Omron CX-Programmer project 新規ﾌﾟﾛｼﾞｪｸﾄ (CX-Programmer 9.76)

# PLC 新規PLC1: CJ2M CPU11
I/O table (CPU CJ2M-CPU11): rack 0 slot 0 CJ1W-ETN21(ETN21Mode)

## Program 新規ﾌﾟﾛｸﾞﾗﾑ1 (cyclic task 0)
Local symbols
ETN_TCPｺﾈｸｼｮﾝ状態 D30016 UINT  ; ETNﾕﾆｯﾄ用TCPｺﾈｸｼｮﾝ状態
ETN_TCP受信ﾃﾞｰﾀﾊﾞｲﾄ数 D30008 UINT  ; ETNﾕﾆｯﾄ用TCP受信ﾃﾞｰﾀﾊﾞｲﾄ数
ETN_ｵｰﾌﾟﾝ要求 1522.10 BOOL  ; ETNﾕﾆｯﾄ用TCPｵｰﾌﾟﾝ要求(ACTIVE)特定ﾋﾞｯﾄ
ETN_ｸﾛｰｽﾞ要求 1522.13 BOOL  ; ETNﾕﾆｯﾄ用ｸﾛｰｽﾞ要求特定ﾋﾞｯﾄ
ETN_ｿｹｯﾄNo8 D30088 UINT  ; ETNﾕﾆｯﾄ用ｿｹｯﾄｵﾌﾟｼｮﾝ / ｿｹｯﾄNo.8
ETN_ﾀｲﾑｱｳﾄ値 D30096 UINT  ; ETNﾕﾆｯﾄ用ﾀｲﾑｱｳﾄ値
ETN_自ﾎﾟｰﾄNo D30089 UINT  ; ETNﾕﾆｯﾄ用自ﾎﾟｰﾄNo.
ETN_受信ﾃﾞｰﾀあり 1516.13 BOOL  ; ETNﾕﾆｯﾄ用受信ﾃﾞｰﾀあり/なし判定ﾋﾞｯﾄ
ETN_受信要求 1522.12 BOOL  ; ETNﾕﾆｯﾄ用受信要求特定ﾋﾞｯﾄ
ETN_終了ｺｰﾄﾞ D30097 UINT  ; ETNﾕﾆｯﾄ用終了ｺｰﾄﾞ
ETN_相手IPｱﾄﾞﾚｽ_1 D30090 UINT  ; ETNﾕﾆｯﾄ用相手IPｱﾄﾞﾚｽ
ETN_相手IPｱﾄﾞﾚｽ_2 D30091 UINT  ; ETNﾕﾆｯﾄ用相手IPｱﾄﾞﾚｽ
ETN_相手ﾎﾟｰﾄNo D30092 UINT  ; ETNﾕﾆｯﾄ用相手ﾎﾟｰﾄNo.
ETN_送受信ﾃﾞｰﾀｱﾄﾞﾚｽ_1 D30094 UINT  ; ETNﾕﾆｯﾄ用送信/受信ﾃﾞｰﾀｱﾄﾞﾚｽ
ETN_送受信ﾃﾞｰﾀｱﾄﾞﾚｽ_2 D30095 UINT  ; ETNﾕﾆｯﾄ用送信/受信ﾃﾞｰﾀｱﾄﾞﾚｽ
ETN_送受信ﾃﾞｰﾀﾊﾞｲﾄ数 D30093 INT  ; ETNﾕﾆｯﾄ用送信/受信ﾃﾞｰﾀﾊﾞｲﾄ数
ETN_送信要求 1522.11 BOOL  ; ETNﾕﾆｯﾄ用送信要求特定ﾋﾞｯﾄ
出力_ｵｰﾌﾟﾝ異常ｺｰﾄﾞ H400 WORD  ; ｵｰﾌﾟﾝ処理の終了ｺｰﾄﾞ/ﾀｲﾑｱｳﾄｺｰﾄﾞ
出力_ｸﾛｰｽﾞ異常ｺｰﾄﾞ H404 WORD  ; ｸﾛｰｽﾞ処理の終了ｺｰﾄﾞ/ﾀｲﾑｱｳﾄｺｰﾄﾞ
出力_受信ﾃﾞｰﾀ D10001 WORD[2000]  ; 受信ﾃﾞｰﾀ格納ｴﾘｱ
出力_受信ﾃﾞｰﾀﾊﾞｲﾄ数 D10000 INT  ; 受信ﾃﾞｰﾀﾊﾞｲﾄ数格納ｴﾘｱ
出力_受信異常ｺｰﾄﾞ H402 WORD  ; 受信処理の終了ｺｰﾄﾞ/ﾀｲﾑｱｳﾄｺｰﾄﾞ
出力_相手機器異常ｺｰﾄﾞ H403 WORD  ; 相手機器の終了ｺｰﾄﾞ/応答ｺｰﾄﾞ
出力_送信異常ｺｰﾄﾞ H401 WORD  ; 送信処理の終了ｺｰﾄﾞ/ﾀｲﾑｱｳﾄｺｰﾄﾞ
内部_TCPｺﾈｸｼｮﾝ状態 5005 UINT  ; TCPｺﾈｸｼｮﾝ状態判定ｴﾘｱ
内部_ｵｰﾌﾟﾝﾀｲﾑｱｳﾄ 5001.04 BOOL  ; ﾀｲﾑｱｳﾄ
内部_ｵｰﾌﾟﾝ異常終了 5001.02 BOOL  ; 異常終了→【ｸﾛｰｽﾞ処理へ】
内部_ｵｰﾌﾟﾝ監視ﾀｲﾏON T1000 BOOL  ; ｵｰﾌﾟﾝ処理監視ﾀｲﾏ
内部_ｵｰﾌﾟﾝ実行中 5001.00 BOOL  ; ｵｰﾌﾟﾝ処理終了までON状態をKEEP
内部_ｵｰﾌﾟﾝ終了ｺｰﾄﾞ異常 5001.03 BOOL  ; 終了ｺｰﾄﾞ異常
内部_ｵｰﾌﾟﾝ正常終了 5001.01 BOOL  ; 正常終了→【送信処理へ】
内部_ｸﾛｰｽﾞﾀｲﾑｱｳﾄ 5004.04 BOOL  ; ﾀｲﾑｱｳﾄ
内部_ｸﾛｰｽﾞ異常終了 5004.02 BOOL  ; 異常終了→【通信終了】
内部_ｸﾛｰｽﾞ監視ﾀｲﾏON T1003 BOOL  ; ｸﾛｰｽﾞ処理監視ﾀｲﾏ
内部_ｸﾛｰｽﾞ実行中 5004.00 BOOL  ; ｸﾛｰｽﾞ処理終了までON状態をKEEP
内部_ｸﾛｰｽﾞ終了ｺｰﾄﾞ異常 5004.03 BOOL  ; 終了ｺｰﾄﾞ異常
内部_ｸﾛｰｽﾞ状態異常 5004.05 BOOL  ; TCPｸﾛｰｽﾞ状態異常
内部_ｸﾛｰｽﾞ正常終了 5004.01 BOOL  ; 正常終了→【通信終了】
内部_受信ﾀｲﾑｱｳﾄ 5003.04 BOOL  ; ﾀｲﾑｱｳﾄ
内部_受信ﾃﾞｰﾀｱﾄﾞﾚｽ種別 5110 UINT  ; 受信ﾃﾞｰﾀｱﾄﾞﾚｽ種別
内部_受信ﾃﾞｰﾀ先頭CHｱﾄﾞﾚｽ 5111 INT  ; 受信ﾃﾞｰﾀ先頭CHｱﾄﾞﾚｽ
内部_受信ﾃﾞｰﾀ先頭CH増分 5112 INT  ; 受信ﾃﾞｰﾀ先頭CH増分
内部_受信ﾃﾞｰﾀ先頭CH増分余 5113 INT  ; 受信ﾃﾞｰﾀ先頭CH増分余り
内部_受信ﾃﾞｰﾀ判定ｴﾘｱ_UINT 5114 UINT  ; 受信ﾃﾞｰﾀをUINT型に変換し判定に用いるｴﾘｱ
内部_受信異常終了 5003.02 BOOL  ; 異常終了→【ｸﾛｰｽﾞ処理へ】
内部_受信監視ﾀｲﾏON T1002 BOOL  ; 受信処理監視ﾀｲﾏ
内部_受信繰返しON 5003.06 BOOL  ; 受信要求繰返し
内部_受信実行中 5003.00 BOOL  ; 受信処理終了までON状態をKEEP
内部_受信終了ｺｰﾄﾞ異常 5003.03 BOOL  ; 終了ｺｰﾄﾞ異常
内部_受信処理必要 5000.02 BOOL  ; 送信処理後、受信処理を実行する
内部_受信処理不要 5000.03 BOOL  ; 送信処理後、受信処理をｽｷｯﾌﾟし、ｸﾛｰｽﾞ処理を実行する
内部_受信正常終了 5003.01 BOOL  ; 正常終了→【ｸﾛｰｽﾞ処理へ】
内部_受信相手機器異常 5003.05 BOOL  ; 相手機器異常
内部_受信要求ON 5003.07 BOOL  ; 受信要求を繰返し実行するためのON⇔OFFﾋﾞｯﾄ
内部_初期設定終了 5000.04 BOOL  ; 初期設定終了→【ｵｰﾌﾟﾝ処理へ】
内部_送信ﾀｲﾑｱｳﾄ 5002.04 BOOL  ; ﾀｲﾑｱｳﾄ
内部_送信ﾃﾞｰﾀｱﾄﾞﾚｽ種別 5030 UINT  ; 送信ﾃﾞｰﾀｱﾄﾞﾚｽ種別
内部_送信ﾃﾞｰﾀ先頭CHｱﾄﾞﾚｽ 5031 UINT  ; 送信ﾃﾞｰﾀ先頭CHｱﾄﾞﾚｽ
内部_送信異常終了 5002.02 BOOL  ; 異常終了→【ｸﾛｰｽﾞ処理へ】
内部_送信監視ﾀｲﾏON T1001 BOOL  ; 送信処理監視ﾀｲﾏ
内部_送信実行中 5002.00 BOOL  ; 送信処理終了までON状態をKEEP
内部_送信終了ｺｰﾄﾞ異常 5002.03 BOOL  ; 終了ｺｰﾄﾞ異常
内部_送信正常終了 5002.01 BOOL  ; 正常終了→【受信処理へ】
内部_通信実行中 5000.01 BOOL  ; 通信処理終了までON状態をKEEP→【ｵｰﾌﾟﾝ処理へ】
入力_ｵｰﾌﾟﾝ監視時間_BCD 5010 UINT_BCD  ; ｵｰﾌﾟﾝ監視時間（BCD)
入力_ｸﾛｰｽﾞ監視時間_BCD 5013 UINT_BCD  ; ｸﾛｰｽﾞ監視時間（BCD)
入力_起動 5000.00 BOOL  ; 通信処理を開始するためのｽｲｯﾁ（手動にてONする）
入力_受信監視時間_BCD 5012 UINT_BCD  ; 受信監視時間（BCD)
入力_受信処理要否 5020 UINT  ; 送信処理に対し受信処理が必要か否かの設定
入力_受信待機時間_BIN 5014 UINT  ; 受信待機時間（BIN)
入力_送信ﾃﾞｰﾀ D9001 WORD[128]  ; 送信ﾃﾞｰﾀ
入力_送信ﾃﾞｰﾀﾊﾞｲﾄ数 D9000 UINT  ; 送信ﾃﾞｰﾀﾊﾞｲﾄ数
入力_送信監視時間_BCD 5011 UINT_BCD  ; 送信監視時間（BCD)

### Section 起動＆設定

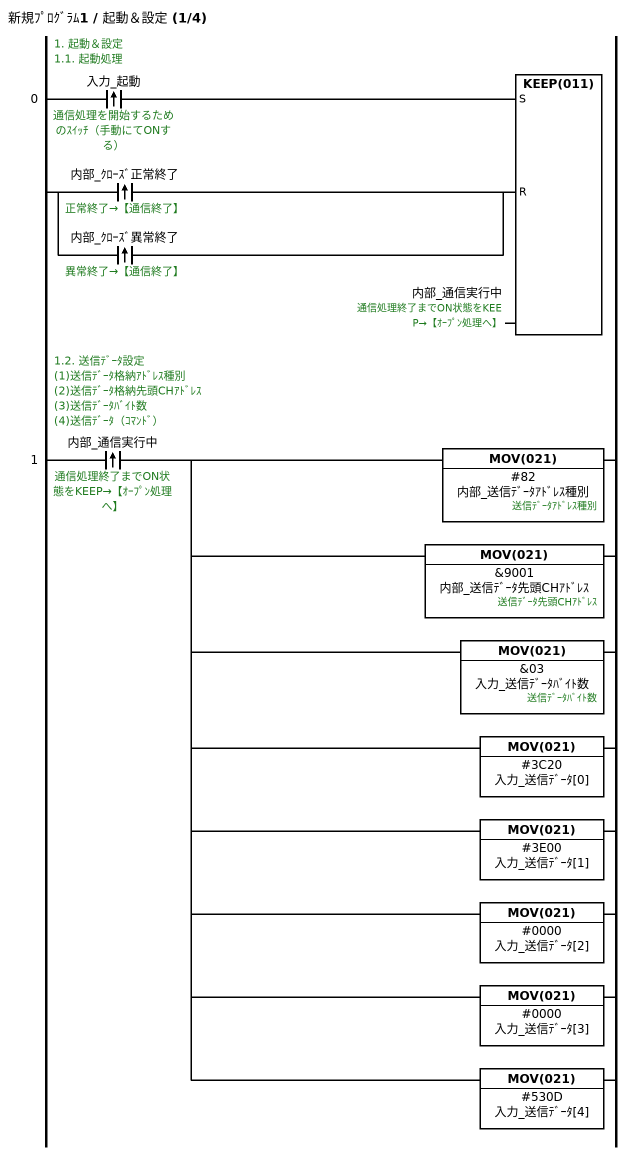
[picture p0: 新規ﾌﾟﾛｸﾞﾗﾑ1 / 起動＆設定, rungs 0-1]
; rung 0: 1. 起動＆設定 / 1.1. 起動処理
@LD 入力_起動  ; 通信処理を開始するためのｽｲｯﾁ（手動にてONする）
@LD 内部_ｸﾛｰｽﾞ正常終了  ; 正常終了→【通信終了】
@OR 内部_ｸﾛｰｽﾞ異常終了  ; 異常終了→【通信終了】
KEEP(011) 内部_通信実行中  ; 通信処理終了までON状態をKEEP→【ｵｰﾌﾟﾝ処理へ】
; rung 1: 1.2. 送信ﾃﾞｰﾀ設定 / (1)送信ﾃﾞｰﾀ格納ｱﾄﾞﾚｽ種別 / (2)送信ﾃﾞｰﾀ格納先頭CHｱﾄﾞﾚｽ / (3)送信ﾃﾞｰﾀﾊﾞｲﾄ数 / (4)送信ﾃﾞｰﾀ（ｺﾏﾝﾄﾞ）
@LD 内部_通信実行中  ; 通信処理終了までON状態をKEEP→【ｵｰﾌﾟﾝ処理へ】
MOV(021) #82 内部_送信ﾃﾞｰﾀｱﾄﾞﾚｽ種別  ; 送信ﾃﾞｰﾀｱﾄﾞﾚｽ種別
MOV(021) &9001 内部_送信ﾃﾞｰﾀ先頭CHｱﾄﾞﾚｽ  ; 送信ﾃﾞｰﾀ先頭CHｱﾄﾞﾚｽ
MOV(021) &03 入力_送信ﾃﾞｰﾀﾊﾞｲﾄ数  ; 送信ﾃﾞｰﾀﾊﾞｲﾄ数
MOV(021) #3C20 入力_送信ﾃﾞｰﾀ[0]
MOV(021) #3E00 入力_送信ﾃﾞｰﾀ[1]
MOV(021) #0000 入力_送信ﾃﾞｰﾀ[2]
MOV(021) #0000 入力_送信ﾃﾞｰﾀ[3]
MOV(021) #530D 入力_送信ﾃﾞｰﾀ[4]

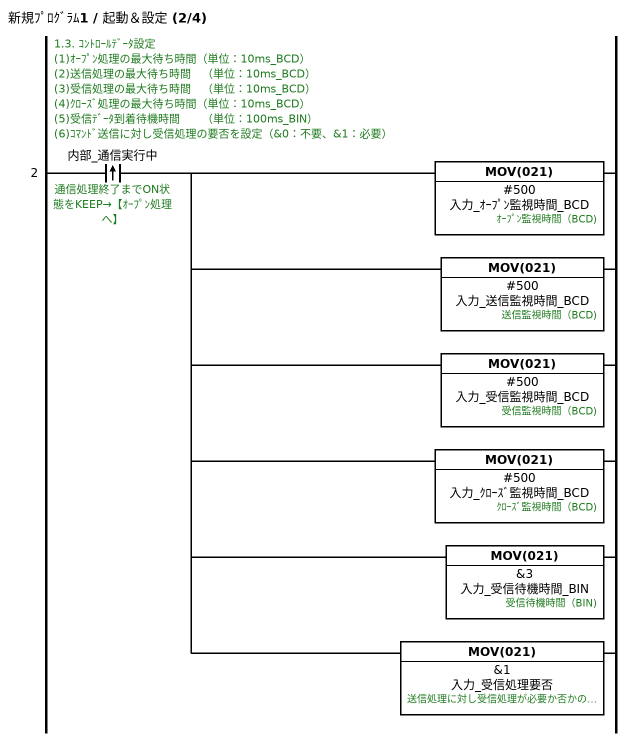
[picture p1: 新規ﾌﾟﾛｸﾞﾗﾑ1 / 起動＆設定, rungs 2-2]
; rung 2: 1.3. ｺﾝﾄﾛｰﾙﾃﾞｰﾀ設定 / (1)ｵｰﾌﾟﾝ処理の最大待ち時間（単位：10ms_BCD） / (2)送信処理の最大待ち時間　（単位：10ms_BCD） / (3)受信処理の最大待ち時間　（単位：10ms_BCD） / (4)ｸﾛｰｽﾞ処理の最大待ち時間（単位：10ms_BCD） / (5)受信ﾃﾞｰﾀ到着待機時間　　（単位：100ms_BIN） / (6)ｺﾏﾝﾄﾞ送信に対し受信処理の要否を設定（&0：不要、&1：必要）
@LD 内部_通信実行中  ; 通信処理終了までON状態をKEEP→【ｵｰﾌﾟﾝ処理へ】
MOV(021) #500 入力_ｵｰﾌﾟﾝ監視時間_BCD  ; ｵｰﾌﾟﾝ監視時間（BCD)
MOV(021) #500 入力_送信監視時間_BCD  ; 送信監視時間（BCD)
MOV(021) #500 入力_受信監視時間_BCD  ; 受信監視時間（BCD)
MOV(021) #500 入力_ｸﾛｰｽﾞ監視時間_BCD  ; ｸﾛｰｽﾞ監視時間（BCD)
MOV(021) &3 入力_受信待機時間_BIN  ; 受信待機時間（BIN)
MOV(021) &1 入力_受信処理要否  ; 送信処理に対し受信処理が必要か否かの設定

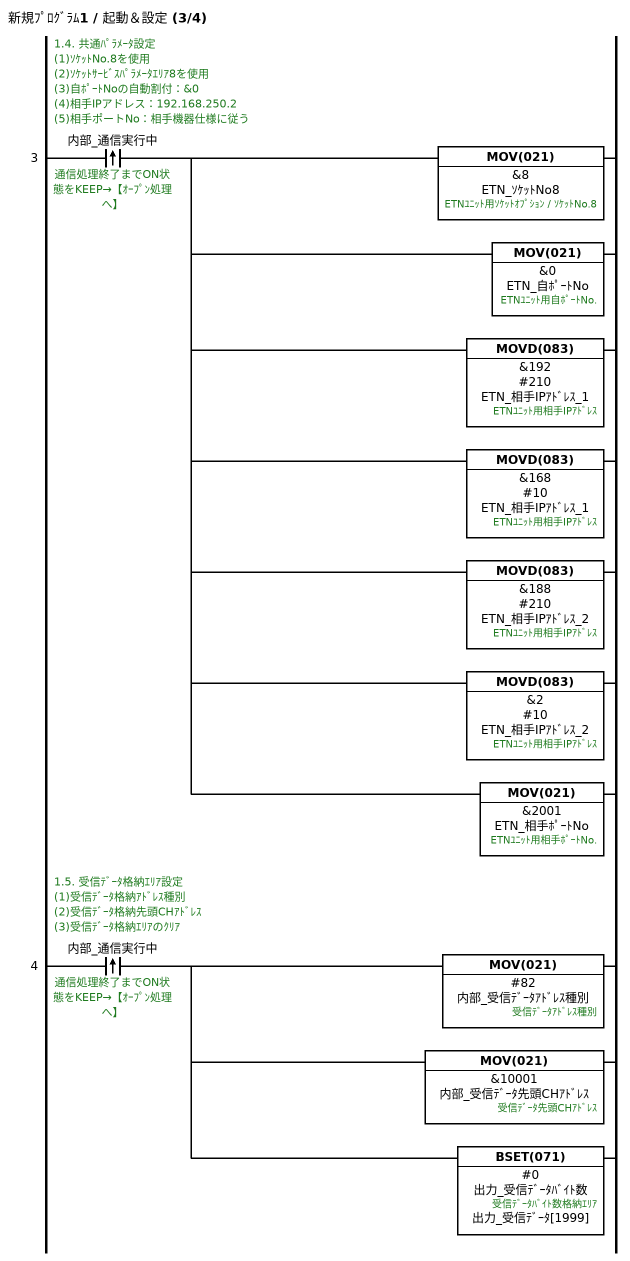
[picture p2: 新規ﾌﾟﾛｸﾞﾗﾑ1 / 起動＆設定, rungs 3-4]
; rung 3: 1.4. 共通ﾊﾟﾗﾒｰﾀ設定 / (1)ｿｹｯﾄNo.8を使用 / (2)ｿｹｯﾄｻｰﾋﾞｽﾊﾟﾗﾒｰﾀｴﾘｱ8を使用 / (3)自ﾎﾟｰﾄNoの自動割付：&0 / (4)相手IPアドレス：192.168.250.2 / (5)相手ポートNo：相手機器仕様に従う
@LD 内部_通信実行中  ; 通信処理終了までON状態をKEEP→【ｵｰﾌﾟﾝ処理へ】
MOV(021) &8 ETN_ｿｹｯﾄNo8  ; ETNﾕﾆｯﾄ用ｿｹｯﾄｵﾌﾟｼｮﾝ / ｿｹｯﾄNo.8
MOV(021) &0 ETN_自ﾎﾟｰﾄNo  ; ETNﾕﾆｯﾄ用自ﾎﾟｰﾄNo.
MOVD(083) &192 #210 ETN_相手IPｱﾄﾞﾚｽ_1  ; ETNﾕﾆｯﾄ用相手IPｱﾄﾞﾚｽ
MOVD(083) &168 #10 ETN_相手IPｱﾄﾞﾚｽ_1  ; ETNﾕﾆｯﾄ用相手IPｱﾄﾞﾚｽ
MOVD(083) &188 #210 ETN_相手IPｱﾄﾞﾚｽ_2  ; ETNﾕﾆｯﾄ用相手IPｱﾄﾞﾚｽ
MOVD(083) &2 #10 ETN_相手IPｱﾄﾞﾚｽ_2  ; ETNﾕﾆｯﾄ用相手IPｱﾄﾞﾚｽ
MOV(021) &2001 ETN_相手ﾎﾟｰﾄNo  ; ETNﾕﾆｯﾄ用相手ﾎﾟｰﾄNo.
; rung 4: 1.5. 受信ﾃﾞｰﾀ格納ｴﾘｱ設定 / (1)受信ﾃﾞｰﾀ格納ｱﾄﾞﾚｽ種別 / (2)受信ﾃﾞｰﾀ格納先頭CHｱﾄﾞﾚｽ / (3)受信ﾃﾞｰﾀ格納ｴﾘｱのｸﾘｱ
@LD 内部_通信実行中  ; 通信処理終了までON状態をKEEP→【ｵｰﾌﾟﾝ処理へ】
MOV(021) #82 内部_受信ﾃﾞｰﾀｱﾄﾞﾚｽ種別  ; 受信ﾃﾞｰﾀｱﾄﾞﾚｽ種別
MOV(021) &10001 内部_受信ﾃﾞｰﾀ先頭CHｱﾄﾞﾚｽ  ; 受信ﾃﾞｰﾀ先頭CHｱﾄﾞﾚｽ
BSET(071) #0 出力_受信ﾃﾞｰﾀﾊﾞｲﾄ数 出力_受信ﾃﾞｰﾀ[1999]  ; 受信ﾃﾞｰﾀﾊﾞｲﾄ数格納ｴﾘｱ

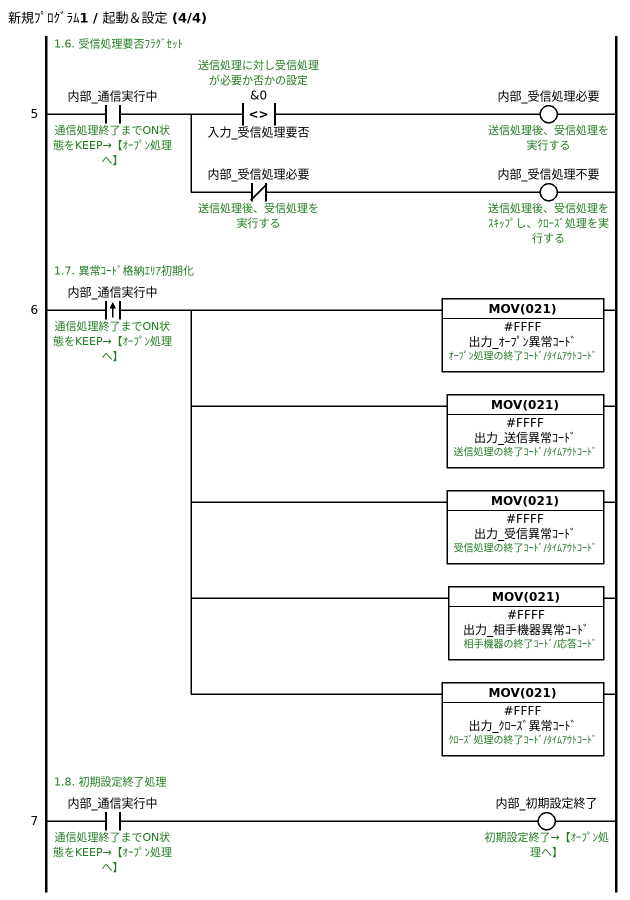
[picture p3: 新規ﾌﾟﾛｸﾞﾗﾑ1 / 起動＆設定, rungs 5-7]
; rung 5: 1.6. 受信処理要否ﾌﾗｸﾞｾｯﾄ
LD 内部_通信実行中  ; 通信処理終了までON状態をKEEP→【ｵｰﾌﾟﾝ処理へ】
OUT TR0
AND<>(305) &0 入力_受信処理要否  ; 送信処理に対し受信処理が必要か否かの設定
OUT 内部_受信処理必要  ; 送信処理後、受信処理を実行する
LD TR0
ANDNOT 内部_受信処理必要  ; 送信処理後、受信処理を実行する
OUT 内部_受信処理不要  ; 送信処理後、受信処理をｽｷｯﾌﾟし、ｸﾛｰｽﾞ処理を実行する
; rung 6: 1.7. 異常ｺｰﾄﾞ格納ｴﾘｱ初期化
@LD 内部_通信実行中  ; 通信処理終了までON状態をKEEP→【ｵｰﾌﾟﾝ処理へ】
MOV(021) #FFFF 出力_ｵｰﾌﾟﾝ異常ｺｰﾄﾞ  ; ｵｰﾌﾟﾝ処理の終了ｺｰﾄﾞ/ﾀｲﾑｱｳﾄｺｰﾄﾞ
MOV(021) #FFFF 出力_送信異常ｺｰﾄﾞ  ; 送信処理の終了ｺｰﾄﾞ/ﾀｲﾑｱｳﾄｺｰﾄﾞ
MOV(021) #FFFF 出力_受信異常ｺｰﾄﾞ  ; 受信処理の終了ｺｰﾄﾞ/ﾀｲﾑｱｳﾄｺｰﾄﾞ
MOV(021) #FFFF 出力_相手機器異常ｺｰﾄﾞ  ; 相手機器の終了ｺｰﾄﾞ/応答ｺｰﾄﾞ
MOV(021) #FFFF 出力_ｸﾛｰｽﾞ異常ｺｰﾄﾞ  ; ｸﾛｰｽﾞ処理の終了ｺｰﾄﾞ/ﾀｲﾑｱｳﾄｺｰﾄﾞ
; rung 7: 1.8. 初期設定終了処理
LD 内部_通信実行中  ; 通信処理終了までON状態をKEEP→【ｵｰﾌﾟﾝ処理へ】
OUT 内部_初期設定終了  ; 初期設定終了→【ｵｰﾌﾟﾝ処理へ】

### Section ｵｰﾌﾟﾝ処理

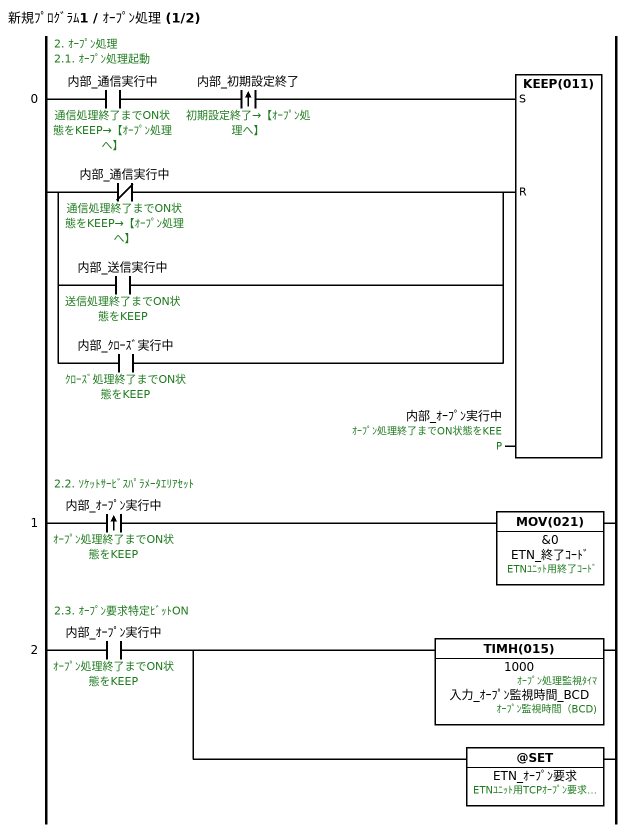
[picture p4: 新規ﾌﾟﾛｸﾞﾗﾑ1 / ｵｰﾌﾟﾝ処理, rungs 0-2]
; rung 0: 2. ｵｰﾌﾟﾝ処理 / 2.1. ｵｰﾌﾟﾝ処理起動
LD 内部_通信実行中  ; 通信処理終了までON状態をKEEP→【ｵｰﾌﾟﾝ処理へ】
@AND 内部_初期設定終了  ; 初期設定終了→【ｵｰﾌﾟﾝ処理へ】
LDNOT 内部_通信実行中  ; 通信処理終了までON状態をKEEP→【ｵｰﾌﾟﾝ処理へ】
OR 内部_送信実行中  ; 送信処理終了までON状態をKEEP
OR 内部_ｸﾛｰｽﾞ実行中  ; ｸﾛｰｽﾞ処理終了までON状態をKEEP
KEEP(011) 内部_ｵｰﾌﾟﾝ実行中  ; ｵｰﾌﾟﾝ処理終了までON状態をKEEP
; rung 1: 2.2. ｿｹｯﾄｻｰﾋﾞｽﾊﾟﾗﾒｰﾀｴﾘｱｾｯﾄ
@LD 内部_ｵｰﾌﾟﾝ実行中  ; ｵｰﾌﾟﾝ処理終了までON状態をKEEP
MOV(021) &0 ETN_終了ｺｰﾄﾞ  ; ETNﾕﾆｯﾄ用終了ｺｰﾄﾞ
; rung 2: 2.3. ｵｰﾌﾟﾝ要求特定ﾋﾞｯﾄON
LD 内部_ｵｰﾌﾟﾝ実行中  ; ｵｰﾌﾟﾝ処理終了までON状態をKEEP
TIMH(015) 1000 入力_ｵｰﾌﾟﾝ監視時間_BCD  ; ｵｰﾌﾟﾝ監視時間（BCD), ｵｰﾌﾟﾝ処理監視ﾀｲﾏ
@SET ETN_ｵｰﾌﾟﾝ要求  ; ETNﾕﾆｯﾄ用TCPｵｰﾌﾟﾝ要求(ACTIVE)特定ﾋﾞｯﾄ

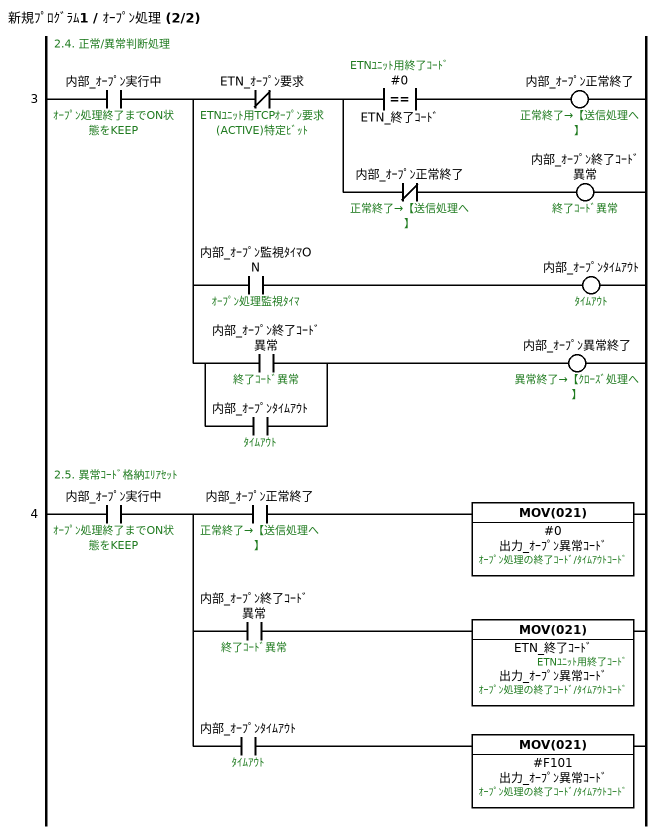
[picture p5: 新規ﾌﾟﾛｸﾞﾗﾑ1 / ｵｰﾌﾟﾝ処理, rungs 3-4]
; rung 3: 2.4. 正常/異常判断処理
LD 内部_ｵｰﾌﾟﾝ実行中  ; ｵｰﾌﾟﾝ処理終了までON状態をKEEP
OUT TR0
ANDNOT ETN_ｵｰﾌﾟﾝ要求  ; ETNﾕﾆｯﾄ用TCPｵｰﾌﾟﾝ要求(ACTIVE)特定ﾋﾞｯﾄ
OUT TR1
AND=(300) #0 ETN_終了ｺｰﾄﾞ  ; ETNﾕﾆｯﾄ用終了ｺｰﾄﾞ
OUT 内部_ｵｰﾌﾟﾝ正常終了  ; 正常終了→【送信処理へ】
LD TR1
ANDNOT 内部_ｵｰﾌﾟﾝ正常終了  ; 正常終了→【送信処理へ】
OUT 内部_ｵｰﾌﾟﾝ終了ｺｰﾄﾞ異常  ; 終了ｺｰﾄﾞ異常
LD TR0
AND 内部_ｵｰﾌﾟﾝ監視ﾀｲﾏON  ; ｵｰﾌﾟﾝ処理監視ﾀｲﾏ
OUT 内部_ｵｰﾌﾟﾝﾀｲﾑｱｳﾄ  ; ﾀｲﾑｱｳﾄ
LD TR0
LD 内部_ｵｰﾌﾟﾝ終了ｺｰﾄﾞ異常  ; 終了ｺｰﾄﾞ異常
OR 内部_ｵｰﾌﾟﾝﾀｲﾑｱｳﾄ  ; ﾀｲﾑｱｳﾄ
ANDLD
OUT 内部_ｵｰﾌﾟﾝ異常終了  ; 異常終了→【ｸﾛｰｽﾞ処理へ】
; rung 4: 2.5. 異常ｺｰﾄﾞ格納ｴﾘｱｾｯﾄ
LD 内部_ｵｰﾌﾟﾝ実行中  ; ｵｰﾌﾟﾝ処理終了までON状態をKEEP
OUT TR0
AND 内部_ｵｰﾌﾟﾝ正常終了  ; 正常終了→【送信処理へ】
MOV(021) #0 出力_ｵｰﾌﾟﾝ異常ｺｰﾄﾞ  ; ｵｰﾌﾟﾝ処理の終了ｺｰﾄﾞ/ﾀｲﾑｱｳﾄｺｰﾄﾞ
LD TR0
AND 内部_ｵｰﾌﾟﾝ終了ｺｰﾄﾞ異常  ; 終了ｺｰﾄﾞ異常
MOV(021) ETN_終了ｺｰﾄﾞ 出力_ｵｰﾌﾟﾝ異常ｺｰﾄﾞ  ; ETNﾕﾆｯﾄ用終了ｺｰﾄﾞ, ｵｰﾌﾟﾝ処理の終了ｺｰﾄﾞ/ﾀｲﾑｱｳﾄｺｰﾄﾞ
LD TR0
AND 内部_ｵｰﾌﾟﾝﾀｲﾑｱｳﾄ  ; ﾀｲﾑｱｳﾄ
MOV(021) #F101 出力_ｵｰﾌﾟﾝ異常ｺｰﾄﾞ  ; ｵｰﾌﾟﾝ処理の終了ｺｰﾄﾞ/ﾀｲﾑｱｳﾄｺｰﾄﾞ

### Section 送信処理

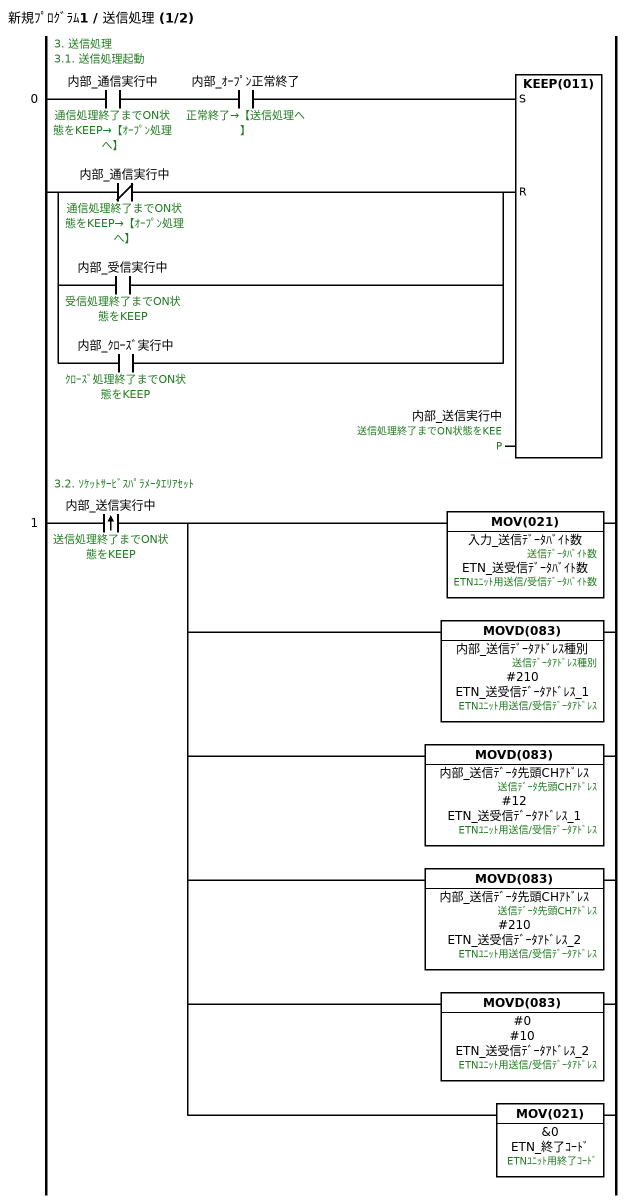
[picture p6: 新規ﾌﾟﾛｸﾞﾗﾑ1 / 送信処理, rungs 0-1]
; rung 0: 3. 送信処理 / 3.1. 送信処理起動
LD 内部_通信実行中  ; 通信処理終了までON状態をKEEP→【ｵｰﾌﾟﾝ処理へ】
AND 内部_ｵｰﾌﾟﾝ正常終了  ; 正常終了→【送信処理へ】
LDNOT 内部_通信実行中  ; 通信処理終了までON状態をKEEP→【ｵｰﾌﾟﾝ処理へ】
OR 内部_受信実行中  ; 受信処理終了までON状態をKEEP
OR 内部_ｸﾛｰｽﾞ実行中  ; ｸﾛｰｽﾞ処理終了までON状態をKEEP
KEEP(011) 内部_送信実行中  ; 送信処理終了までON状態をKEEP
; rung 1: 3.2. ｿｹｯﾄｻｰﾋﾞｽﾊﾟﾗﾒｰﾀｴﾘｱｾｯﾄ
@LD 内部_送信実行中  ; 送信処理終了までON状態をKEEP
MOV(021) 入力_送信ﾃﾞｰﾀﾊﾞｲﾄ数 ETN_送受信ﾃﾞｰﾀﾊﾞｲﾄ数  ; 送信ﾃﾞｰﾀﾊﾞｲﾄ数, ETNﾕﾆｯﾄ用送信/受信ﾃﾞｰﾀﾊﾞｲﾄ数
MOVD(083) 内部_送信ﾃﾞｰﾀｱﾄﾞﾚｽ種別 #210 ETN_送受信ﾃﾞｰﾀｱﾄﾞﾚｽ_1  ; 送信ﾃﾞｰﾀｱﾄﾞﾚｽ種別, ETNﾕﾆｯﾄ用送信/受信ﾃﾞｰﾀｱﾄﾞﾚｽ
MOVD(083) 内部_送信ﾃﾞｰﾀ先頭CHｱﾄﾞﾚｽ #12 ETN_送受信ﾃﾞｰﾀｱﾄﾞﾚｽ_1  ; 送信ﾃﾞｰﾀ先頭CHｱﾄﾞﾚｽ, ETNﾕﾆｯﾄ用送信/受信ﾃﾞｰﾀｱﾄﾞﾚｽ
MOVD(083) 内部_送信ﾃﾞｰﾀ先頭CHｱﾄﾞﾚｽ #210 ETN_送受信ﾃﾞｰﾀｱﾄﾞﾚｽ_2  ; 送信ﾃﾞｰﾀ先頭CHｱﾄﾞﾚｽ, ETNﾕﾆｯﾄ用送信/受信ﾃﾞｰﾀｱﾄﾞﾚｽ
MOVD(083) #0 #10 ETN_送受信ﾃﾞｰﾀｱﾄﾞﾚｽ_2  ; ETNﾕﾆｯﾄ用送信/受信ﾃﾞｰﾀｱﾄﾞﾚｽ
MOV(021) &0 ETN_終了ｺｰﾄﾞ  ; ETNﾕﾆｯﾄ用終了ｺｰﾄﾞ

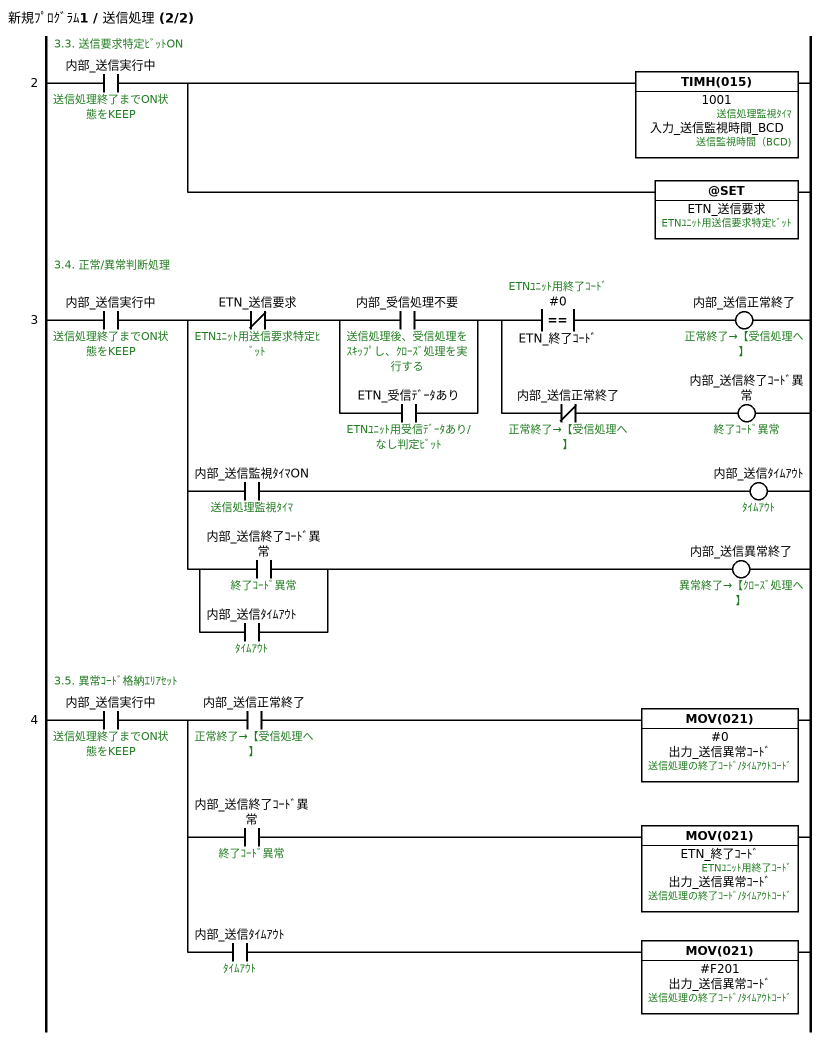
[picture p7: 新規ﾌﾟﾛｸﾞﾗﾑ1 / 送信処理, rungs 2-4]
; rung 2: 3.3. 送信要求特定ﾋﾞｯﾄON
LD 内部_送信実行中  ; 送信処理終了までON状態をKEEP
TIMH(015) 1001 入力_送信監視時間_BCD  ; 送信監視時間（BCD), 送信処理監視ﾀｲﾏ
@SET ETN_送信要求  ; ETNﾕﾆｯﾄ用送信要求特定ﾋﾞｯﾄ
; rung 3: 3.4. 正常/異常判断処理
LD 内部_送信実行中  ; 送信処理終了までON状態をKEEP
OUT TR0
ANDNOT ETN_送信要求  ; ETNﾕﾆｯﾄ用送信要求特定ﾋﾞｯﾄ
LD 内部_受信処理不要  ; 送信処理後、受信処理をｽｷｯﾌﾟし、ｸﾛｰｽﾞ処理を実行する
OR ETN_受信ﾃﾞｰﾀあり  ; ETNﾕﾆｯﾄ用受信ﾃﾞｰﾀあり/なし判定ﾋﾞｯﾄ
ANDLD
OUT TR1
AND=(300) #0 ETN_終了ｺｰﾄﾞ  ; ETNﾕﾆｯﾄ用終了ｺｰﾄﾞ
OUT 内部_送信正常終了  ; 正常終了→【受信処理へ】
LD TR1
ANDNOT 内部_送信正常終了  ; 正常終了→【受信処理へ】
OUT 内部_送信終了ｺｰﾄﾞ異常  ; 終了ｺｰﾄﾞ異常
LD TR0
AND 内部_送信監視ﾀｲﾏON  ; 送信処理監視ﾀｲﾏ
OUT 内部_送信ﾀｲﾑｱｳﾄ  ; ﾀｲﾑｱｳﾄ
LD TR0
LD 内部_送信終了ｺｰﾄﾞ異常  ; 終了ｺｰﾄﾞ異常
OR 内部_送信ﾀｲﾑｱｳﾄ  ; ﾀｲﾑｱｳﾄ
ANDLD
OUT 内部_送信異常終了  ; 異常終了→【ｸﾛｰｽﾞ処理へ】
; rung 4: 3.5. 異常ｺｰﾄﾞ格納ｴﾘｱｾｯﾄ
LD 内部_送信実行中  ; 送信処理終了までON状態をKEEP
OUT TR0
AND 内部_送信正常終了  ; 正常終了→【受信処理へ】
MOV(021) #0 出力_送信異常ｺｰﾄﾞ  ; 送信処理の終了ｺｰﾄﾞ/ﾀｲﾑｱｳﾄｺｰﾄﾞ
LD TR0
AND 内部_送信終了ｺｰﾄﾞ異常  ; 終了ｺｰﾄﾞ異常
MOV(021) ETN_終了ｺｰﾄﾞ 出力_送信異常ｺｰﾄﾞ  ; ETNﾕﾆｯﾄ用終了ｺｰﾄﾞ, 送信処理の終了ｺｰﾄﾞ/ﾀｲﾑｱｳﾄｺｰﾄﾞ
LD TR0
AND 内部_送信ﾀｲﾑｱｳﾄ  ; ﾀｲﾑｱｳﾄ
MOV(021) #F201 出力_送信異常ｺｰﾄﾞ  ; 送信処理の終了ｺｰﾄﾞ/ﾀｲﾑｱｳﾄｺｰﾄﾞ

### Section 受信処理

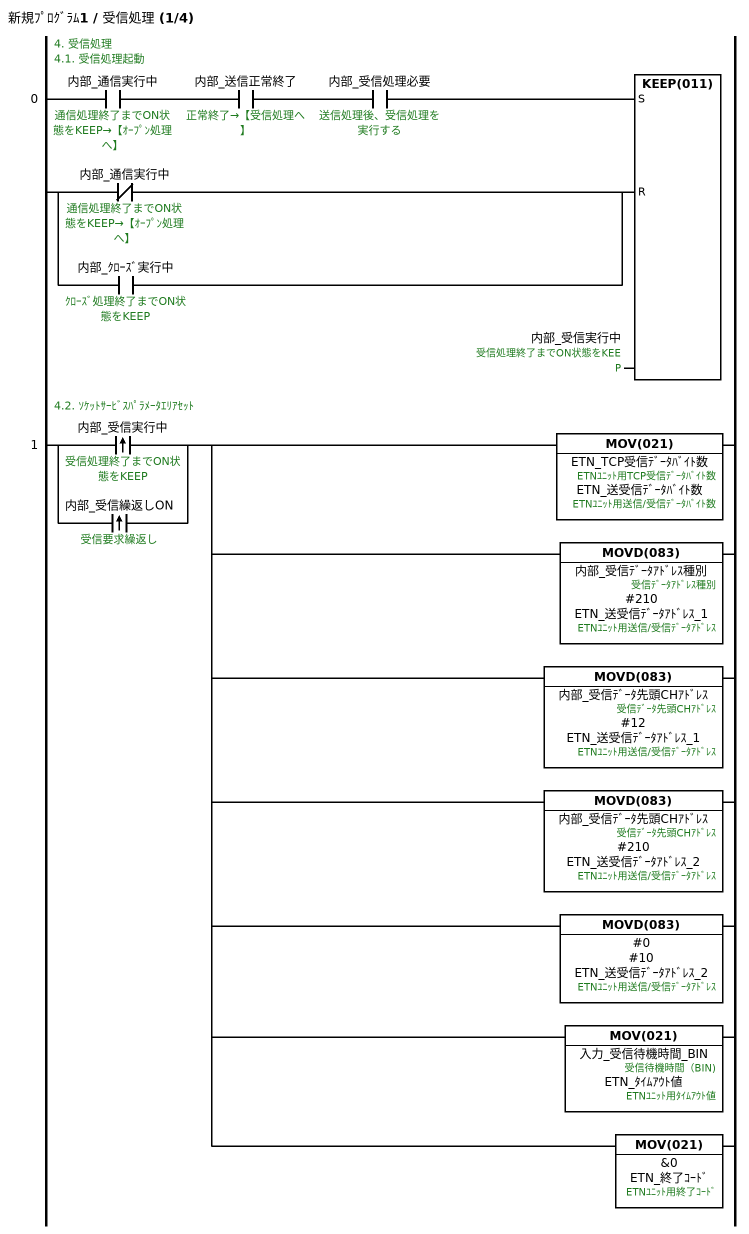
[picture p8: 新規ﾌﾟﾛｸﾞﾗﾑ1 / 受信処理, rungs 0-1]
; rung 0: 4. 受信処理 / 4.1. 受信処理起動
LD 内部_通信実行中  ; 通信処理終了までON状態をKEEP→【ｵｰﾌﾟﾝ処理へ】
AND 内部_送信正常終了  ; 正常終了→【受信処理へ】
AND 内部_受信処理必要  ; 送信処理後、受信処理を実行する
LDNOT 内部_通信実行中  ; 通信処理終了までON状態をKEEP→【ｵｰﾌﾟﾝ処理へ】
OR 内部_ｸﾛｰｽﾞ実行中  ; ｸﾛｰｽﾞ処理終了までON状態をKEEP
KEEP(011) 内部_受信実行中  ; 受信処理終了までON状態をKEEP
; rung 1: 4.2. ｿｹｯﾄｻｰﾋﾞｽﾊﾟﾗﾒｰﾀｴﾘｱｾｯﾄ
@LD 内部_受信実行中  ; 受信処理終了までON状態をKEEP
@OR 内部_受信繰返しON  ; 受信要求繰返し
MOV(021) ETN_TCP受信ﾃﾞｰﾀﾊﾞｲﾄ数 ETN_送受信ﾃﾞｰﾀﾊﾞｲﾄ数  ; ETNﾕﾆｯﾄ用TCP受信ﾃﾞｰﾀﾊﾞｲﾄ数, ETNﾕﾆｯﾄ用送信/受信ﾃﾞｰﾀﾊﾞｲﾄ数
MOVD(083) 内部_受信ﾃﾞｰﾀｱﾄﾞﾚｽ種別 #210 ETN_送受信ﾃﾞｰﾀｱﾄﾞﾚｽ_1  ; 受信ﾃﾞｰﾀｱﾄﾞﾚｽ種別, ETNﾕﾆｯﾄ用送信/受信ﾃﾞｰﾀｱﾄﾞﾚｽ
MOVD(083) 内部_受信ﾃﾞｰﾀ先頭CHｱﾄﾞﾚｽ #12 ETN_送受信ﾃﾞｰﾀｱﾄﾞﾚｽ_1  ; 受信ﾃﾞｰﾀ先頭CHｱﾄﾞﾚｽ, ETNﾕﾆｯﾄ用送信/受信ﾃﾞｰﾀｱﾄﾞﾚｽ
MOVD(083) 内部_受信ﾃﾞｰﾀ先頭CHｱﾄﾞﾚｽ #210 ETN_送受信ﾃﾞｰﾀｱﾄﾞﾚｽ_2  ; 受信ﾃﾞｰﾀ先頭CHｱﾄﾞﾚｽ, ETNﾕﾆｯﾄ用送信/受信ﾃﾞｰﾀｱﾄﾞﾚｽ
MOVD(083) #0 #10 ETN_送受信ﾃﾞｰﾀｱﾄﾞﾚｽ_2  ; ETNﾕﾆｯﾄ用送信/受信ﾃﾞｰﾀｱﾄﾞﾚｽ
MOV(021) 入力_受信待機時間_BIN ETN_ﾀｲﾑｱｳﾄ値  ; 受信待機時間（BIN), ETNﾕﾆｯﾄ用ﾀｲﾑｱｳﾄ値
MOV(021) &0 ETN_終了ｺｰﾄﾞ  ; ETNﾕﾆｯﾄ用終了ｺｰﾄﾞ

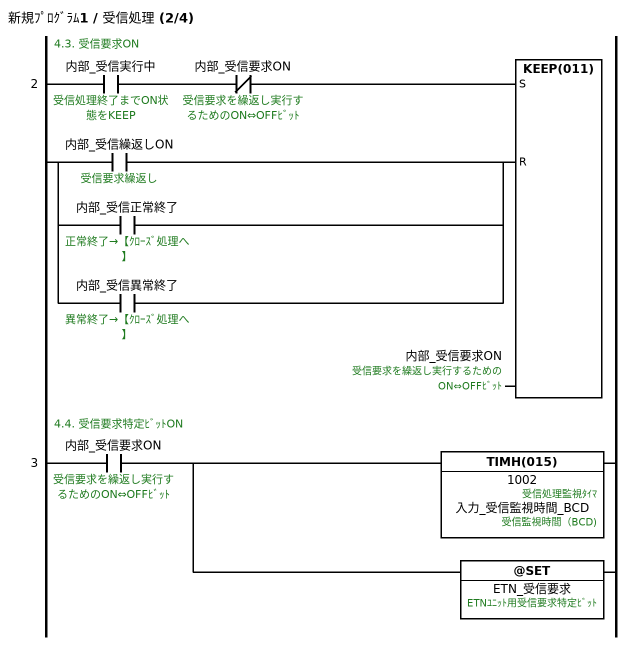
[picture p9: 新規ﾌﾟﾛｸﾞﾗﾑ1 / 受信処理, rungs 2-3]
; rung 2: 4.3. 受信要求ON
LD 内部_受信実行中  ; 受信処理終了までON状態をKEEP
ANDNOT 内部_受信要求ON  ; 受信要求を繰返し実行するためのON⇔OFFﾋﾞｯﾄ
LD 内部_受信繰返しON  ; 受信要求繰返し
OR 内部_受信正常終了  ; 正常終了→【ｸﾛｰｽﾞ処理へ】
OR 内部_受信異常終了  ; 異常終了→【ｸﾛｰｽﾞ処理へ】
KEEP(011) 内部_受信要求ON  ; 受信要求を繰返し実行するためのON⇔OFFﾋﾞｯﾄ
; rung 3: 4.4. 受信要求特定ﾋﾞｯﾄON
LD 内部_受信要求ON  ; 受信要求を繰返し実行するためのON⇔OFFﾋﾞｯﾄ
TIMH(015) 1002 入力_受信監視時間_BCD  ; 受信監視時間（BCD), 受信処理監視ﾀｲﾏ
@SET ETN_受信要求  ; ETNﾕﾆｯﾄ用受信要求特定ﾋﾞｯﾄ

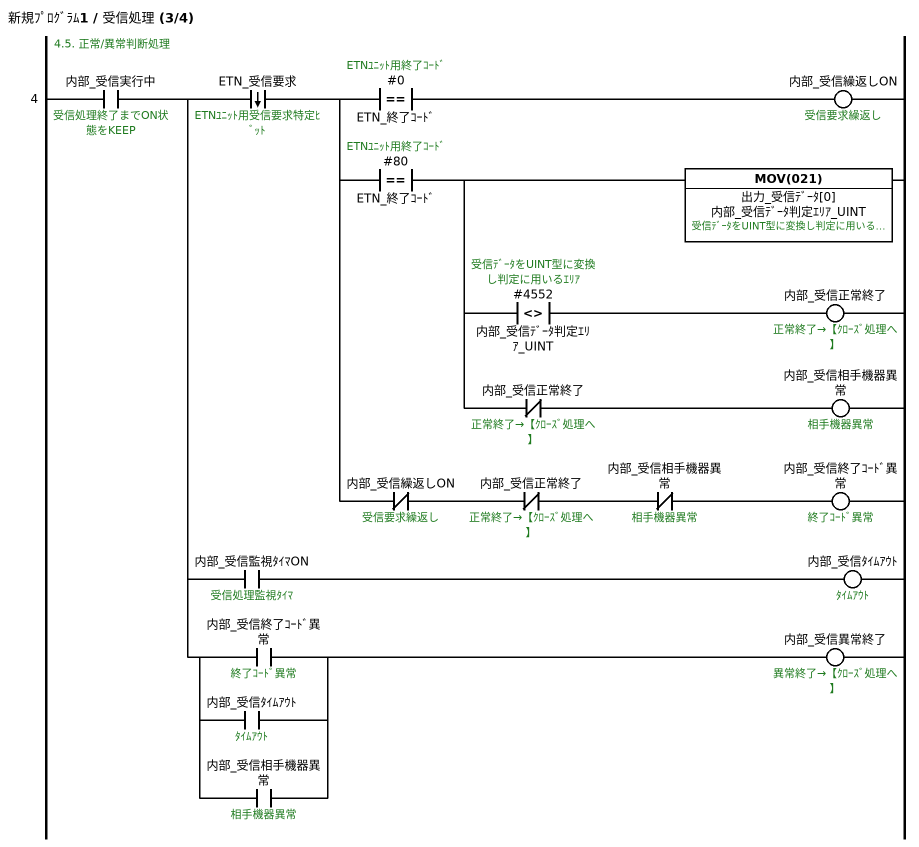
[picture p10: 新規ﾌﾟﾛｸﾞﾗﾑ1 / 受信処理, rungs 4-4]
; rung 4: 4.5. 正常/異常判断処理
LD 内部_受信実行中  ; 受信処理終了までON状態をKEEP
OUT TR0
%AND ETN_受信要求  ; ETNﾕﾆｯﾄ用受信要求特定ﾋﾞｯﾄ
OUT TR1
AND=(300) #0 ETN_終了ｺｰﾄﾞ  ; ETNﾕﾆｯﾄ用終了ｺｰﾄﾞ
OUT 内部_受信繰返しON  ; 受信要求繰返し
LD TR1
AND=(300) #80 ETN_終了ｺｰﾄﾞ  ; ETNﾕﾆｯﾄ用終了ｺｰﾄﾞ
OUT TR2
MOV(021) 出力_受信ﾃﾞｰﾀ[0] 内部_受信ﾃﾞｰﾀ判定ｴﾘｱ_UINT  ; 受信ﾃﾞｰﾀをUINT型に変換し判定に用いるｴﾘｱ
AND<>(305) #4552 内部_受信ﾃﾞｰﾀ判定ｴﾘｱ_UINT  ; 受信ﾃﾞｰﾀをUINT型に変換し判定に用いるｴﾘｱ
OUT 内部_受信正常終了  ; 正常終了→【ｸﾛｰｽﾞ処理へ】
LD TR2
ANDNOT 内部_受信正常終了  ; 正常終了→【ｸﾛｰｽﾞ処理へ】
OUT 内部_受信相手機器異常  ; 相手機器異常
LD TR1
ANDNOT 内部_受信繰返しON  ; 受信要求繰返し
ANDNOT 内部_受信正常終了  ; 正常終了→【ｸﾛｰｽﾞ処理へ】
ANDNOT 内部_受信相手機器異常  ; 相手機器異常
OUT 内部_受信終了ｺｰﾄﾞ異常  ; 終了ｺｰﾄﾞ異常
LD TR0
AND 内部_受信監視ﾀｲﾏON  ; 受信処理監視ﾀｲﾏ
OUT 内部_受信ﾀｲﾑｱｳﾄ  ; ﾀｲﾑｱｳﾄ
LD TR0
LD 内部_受信終了ｺｰﾄﾞ異常  ; 終了ｺｰﾄﾞ異常
OR 内部_受信ﾀｲﾑｱｳﾄ  ; ﾀｲﾑｱｳﾄ
OR 内部_受信相手機器異常  ; 相手機器異常
ANDLD
OUT 内部_受信異常終了  ; 異常終了→【ｸﾛｰｽﾞ処理へ】

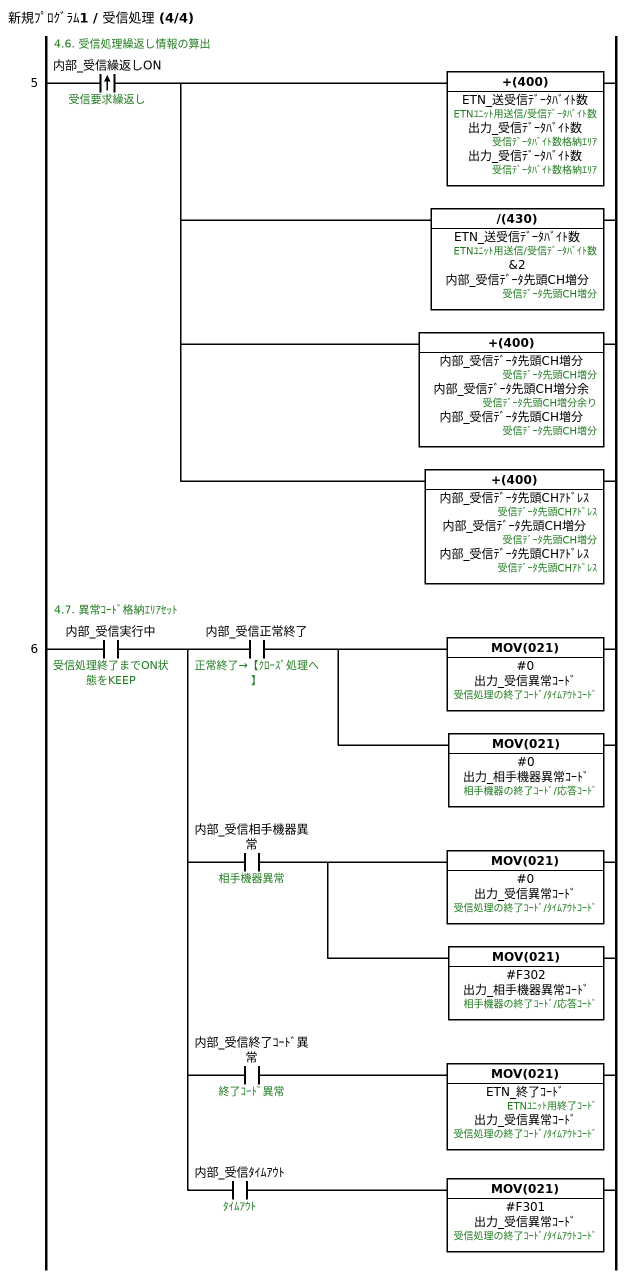
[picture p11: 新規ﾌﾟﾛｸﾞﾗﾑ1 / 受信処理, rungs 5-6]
; rung 5: 4.6. 受信処理繰返し情報の算出
@LD 内部_受信繰返しON  ; 受信要求繰返し
+(400) ETN_送受信ﾃﾞｰﾀﾊﾞｲﾄ数 出力_受信ﾃﾞｰﾀﾊﾞｲﾄ数 出力_受信ﾃﾞｰﾀﾊﾞｲﾄ数  ; ETNﾕﾆｯﾄ用送信/受信ﾃﾞｰﾀﾊﾞｲﾄ数, 受信ﾃﾞｰﾀﾊﾞｲﾄ数格納ｴﾘｱ
/(430) ETN_送受信ﾃﾞｰﾀﾊﾞｲﾄ数 &2 内部_受信ﾃﾞｰﾀ先頭CH増分  ; ETNﾕﾆｯﾄ用送信/受信ﾃﾞｰﾀﾊﾞｲﾄ数, 受信ﾃﾞｰﾀ先頭CH増分
+(400) 内部_受信ﾃﾞｰﾀ先頭CH増分 内部_受信ﾃﾞｰﾀ先頭CH増分余 内部_受信ﾃﾞｰﾀ先頭CH増分  ; 受信ﾃﾞｰﾀ先頭CH増分, 受信ﾃﾞｰﾀ先頭CH増分余り
+(400) 内部_受信ﾃﾞｰﾀ先頭CHｱﾄﾞﾚｽ 内部_受信ﾃﾞｰﾀ先頭CH増分 内部_受信ﾃﾞｰﾀ先頭CHｱﾄﾞﾚｽ  ; 受信ﾃﾞｰﾀ先頭CHｱﾄﾞﾚｽ, 受信ﾃﾞｰﾀ先頭CH増分
; rung 6: 4.7. 異常ｺｰﾄﾞ格納ｴﾘｱｾｯﾄ
LD 内部_受信実行中  ; 受信処理終了までON状態をKEEP
OUT TR0
AND 内部_受信正常終了  ; 正常終了→【ｸﾛｰｽﾞ処理へ】
MOV(021) #0 出力_受信異常ｺｰﾄﾞ  ; 受信処理の終了ｺｰﾄﾞ/ﾀｲﾑｱｳﾄｺｰﾄﾞ
MOV(021) #0 出力_相手機器異常ｺｰﾄﾞ  ; 相手機器の終了ｺｰﾄﾞ/応答ｺｰﾄﾞ
LD TR0
AND 内部_受信相手機器異常  ; 相手機器異常
MOV(021) #0 出力_受信異常ｺｰﾄﾞ  ; 受信処理の終了ｺｰﾄﾞ/ﾀｲﾑｱｳﾄｺｰﾄﾞ
MOV(021) #F302 出力_相手機器異常ｺｰﾄﾞ  ; 相手機器の終了ｺｰﾄﾞ/応答ｺｰﾄﾞ
LD TR0
AND 内部_受信終了ｺｰﾄﾞ異常  ; 終了ｺｰﾄﾞ異常
MOV(021) ETN_終了ｺｰﾄﾞ 出力_受信異常ｺｰﾄﾞ  ; ETNﾕﾆｯﾄ用終了ｺｰﾄﾞ, 受信処理の終了ｺｰﾄﾞ/ﾀｲﾑｱｳﾄｺｰﾄﾞ
LD TR0
AND 内部_受信ﾀｲﾑｱｳﾄ  ; ﾀｲﾑｱｳﾄ
MOV(021) #F301 出力_受信異常ｺｰﾄﾞ  ; 受信処理の終了ｺｰﾄﾞ/ﾀｲﾑｱｳﾄｺｰﾄﾞ

### Section ｸﾛｰｽﾞ処理

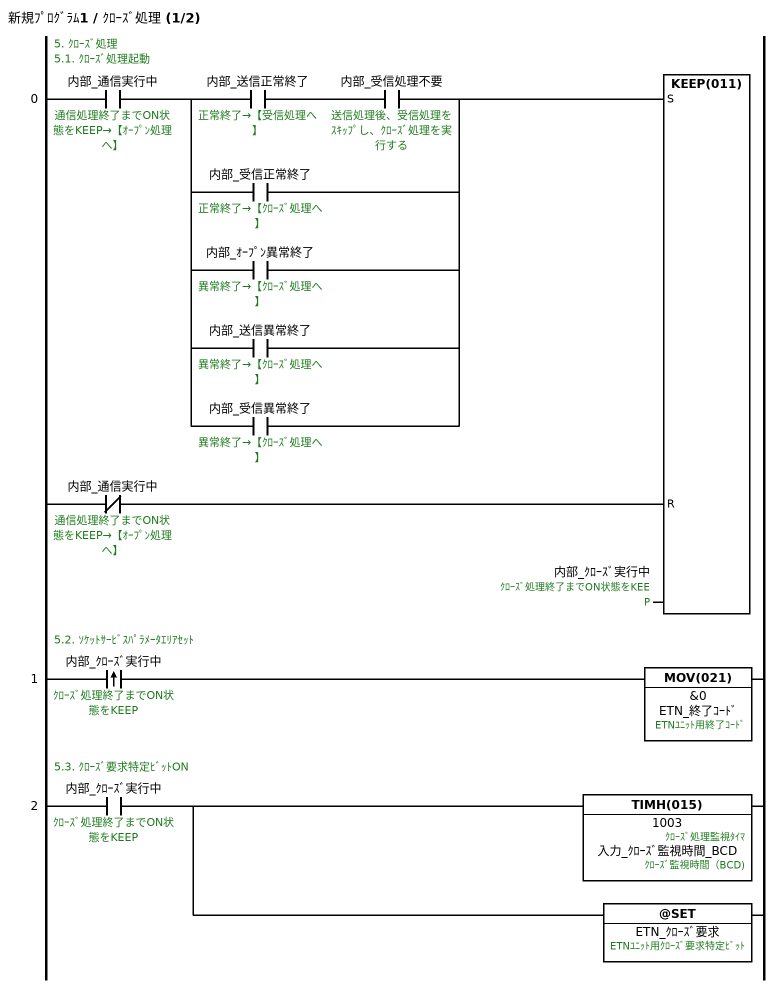
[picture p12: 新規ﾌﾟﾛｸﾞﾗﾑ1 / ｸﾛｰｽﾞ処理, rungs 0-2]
; rung 0: 5. ｸﾛｰｽﾞ処理 / 5.1. ｸﾛｰｽﾞ処理起動
LD 内部_通信実行中  ; 通信処理終了までON状態をKEEP→【ｵｰﾌﾟﾝ処理へ】
LD 内部_送信正常終了  ; 正常終了→【受信処理へ】
AND 内部_受信処理不要  ; 送信処理後、受信処理をｽｷｯﾌﾟし、ｸﾛｰｽﾞ処理を実行する
OR 内部_受信正常終了  ; 正常終了→【ｸﾛｰｽﾞ処理へ】
OR 内部_ｵｰﾌﾟﾝ異常終了  ; 異常終了→【ｸﾛｰｽﾞ処理へ】
OR 内部_送信異常終了  ; 異常終了→【ｸﾛｰｽﾞ処理へ】
OR 内部_受信異常終了  ; 異常終了→【ｸﾛｰｽﾞ処理へ】
ANDLD
LDNOT 内部_通信実行中  ; 通信処理終了までON状態をKEEP→【ｵｰﾌﾟﾝ処理へ】
KEEP(011) 内部_ｸﾛｰｽﾞ実行中  ; ｸﾛｰｽﾞ処理終了までON状態をKEEP
; rung 1: 5.2. ｿｹｯﾄｻｰﾋﾞｽﾊﾟﾗﾒｰﾀｴﾘｱｾｯﾄ
@LD 内部_ｸﾛｰｽﾞ実行中  ; ｸﾛｰｽﾞ処理終了までON状態をKEEP
MOV(021) &0 ETN_終了ｺｰﾄﾞ  ; ETNﾕﾆｯﾄ用終了ｺｰﾄﾞ
; rung 2: 5.3. ｸﾛｰｽﾞ要求特定ﾋﾞｯﾄON
LD 内部_ｸﾛｰｽﾞ実行中  ; ｸﾛｰｽﾞ処理終了までON状態をKEEP
TIMH(015) 1003 入力_ｸﾛｰｽﾞ監視時間_BCD  ; ｸﾛｰｽﾞ監視時間（BCD), ｸﾛｰｽﾞ処理監視ﾀｲﾏ
@SET ETN_ｸﾛｰｽﾞ要求  ; ETNﾕﾆｯﾄ用ｸﾛｰｽﾞ要求特定ﾋﾞｯﾄ

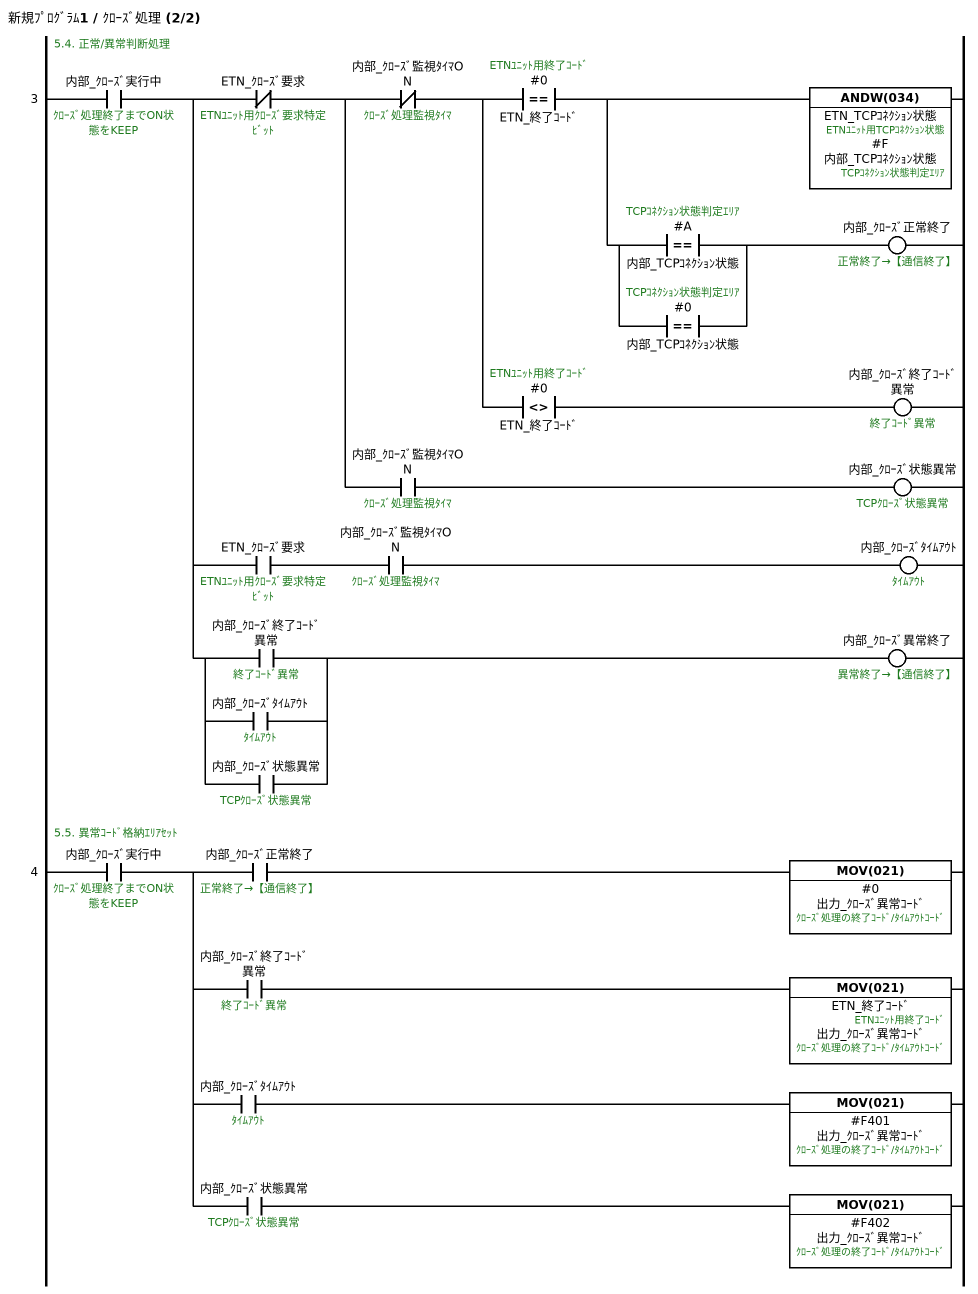
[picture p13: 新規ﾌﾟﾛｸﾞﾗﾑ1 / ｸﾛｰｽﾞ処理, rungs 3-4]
; rung 3: 5.4. 正常/異常判断処理
LD 内部_ｸﾛｰｽﾞ実行中  ; ｸﾛｰｽﾞ処理終了までON状態をKEEP
OUT TR0
ANDNOT ETN_ｸﾛｰｽﾞ要求  ; ETNﾕﾆｯﾄ用ｸﾛｰｽﾞ要求特定ﾋﾞｯﾄ
OUT TR1
ANDNOT 内部_ｸﾛｰｽﾞ監視ﾀｲﾏON  ; ｸﾛｰｽﾞ処理監視ﾀｲﾏ
OUT TR2
AND=(300) #0 ETN_終了ｺｰﾄﾞ  ; ETNﾕﾆｯﾄ用終了ｺｰﾄﾞ
ANDW(034) ETN_TCPｺﾈｸｼｮﾝ状態 #F 内部_TCPｺﾈｸｼｮﾝ状態  ; ETNﾕﾆｯﾄ用TCPｺﾈｸｼｮﾝ状態, TCPｺﾈｸｼｮﾝ状態判定ｴﾘｱ
LD=(300) #A 内部_TCPｺﾈｸｼｮﾝ状態  ; TCPｺﾈｸｼｮﾝ状態判定ｴﾘｱ
OR=(300) #0 内部_TCPｺﾈｸｼｮﾝ状態  ; TCPｺﾈｸｼｮﾝ状態判定ｴﾘｱ
ANDLD
OUT 内部_ｸﾛｰｽﾞ正常終了  ; 正常終了→【通信終了】
LD TR2
AND<>(305) #0 ETN_終了ｺｰﾄﾞ  ; ETNﾕﾆｯﾄ用終了ｺｰﾄﾞ
OUT 内部_ｸﾛｰｽﾞ終了ｺｰﾄﾞ異常  ; 終了ｺｰﾄﾞ異常
LD TR1
AND 内部_ｸﾛｰｽﾞ監視ﾀｲﾏON  ; ｸﾛｰｽﾞ処理監視ﾀｲﾏ
OUT 内部_ｸﾛｰｽﾞ状態異常  ; TCPｸﾛｰｽﾞ状態異常
LD TR0
AND ETN_ｸﾛｰｽﾞ要求  ; ETNﾕﾆｯﾄ用ｸﾛｰｽﾞ要求特定ﾋﾞｯﾄ
AND 内部_ｸﾛｰｽﾞ監視ﾀｲﾏON  ; ｸﾛｰｽﾞ処理監視ﾀｲﾏ
OUT 内部_ｸﾛｰｽﾞﾀｲﾑｱｳﾄ  ; ﾀｲﾑｱｳﾄ
LD TR0
LD 内部_ｸﾛｰｽﾞ終了ｺｰﾄﾞ異常  ; 終了ｺｰﾄﾞ異常
OR 内部_ｸﾛｰｽﾞﾀｲﾑｱｳﾄ  ; ﾀｲﾑｱｳﾄ
OR 内部_ｸﾛｰｽﾞ状態異常  ; TCPｸﾛｰｽﾞ状態異常
ANDLD
OUT 内部_ｸﾛｰｽﾞ異常終了  ; 異常終了→【通信終了】
; rung 4: 5.5. 異常ｺｰﾄﾞ格納ｴﾘｱｾｯﾄ
LD 内部_ｸﾛｰｽﾞ実行中  ; ｸﾛｰｽﾞ処理終了までON状態をKEEP
OUT TR0
AND 内部_ｸﾛｰｽﾞ正常終了  ; 正常終了→【通信終了】
MOV(021) #0 出力_ｸﾛｰｽﾞ異常ｺｰﾄﾞ  ; ｸﾛｰｽﾞ処理の終了ｺｰﾄﾞ/ﾀｲﾑｱｳﾄｺｰﾄﾞ
LD TR0
AND 内部_ｸﾛｰｽﾞ終了ｺｰﾄﾞ異常  ; 終了ｺｰﾄﾞ異常
MOV(021) ETN_終了ｺｰﾄﾞ 出力_ｸﾛｰｽﾞ異常ｺｰﾄﾞ  ; ETNﾕﾆｯﾄ用終了ｺｰﾄﾞ, ｸﾛｰｽﾞ処理の終了ｺｰﾄﾞ/ﾀｲﾑｱｳﾄｺｰﾄﾞ
LD TR0
AND 内部_ｸﾛｰｽﾞﾀｲﾑｱｳﾄ  ; ﾀｲﾑｱｳﾄ
MOV(021) #F401 出力_ｸﾛｰｽﾞ異常ｺｰﾄﾞ  ; ｸﾛｰｽﾞ処理の終了ｺｰﾄﾞ/ﾀｲﾑｱｳﾄｺｰﾄﾞ
LD TR0
AND 内部_ｸﾛｰｽﾞ状態異常  ; TCPｸﾛｰｽﾞ状態異常
MOV(021) #F402 出力_ｸﾛｰｽﾞ異常ｺｰﾄﾞ  ; ｸﾛｰｽﾞ処理の終了ｺｰﾄﾞ/ﾀｲﾑｱｳﾄｺｰﾄﾞ

### Section END
; rung 0
END(001)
